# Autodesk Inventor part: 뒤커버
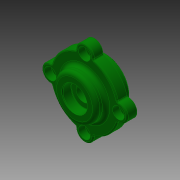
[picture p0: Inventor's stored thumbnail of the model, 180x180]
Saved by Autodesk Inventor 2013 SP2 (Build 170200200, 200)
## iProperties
Created: 2016-05
Part Number: 뒤커버
Document SubType Name: Modeling
Designer: mduedu
Density: 2.71 g/cm^3
Material: 알루미늄 6061
Author: mduedu
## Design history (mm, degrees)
sketch "스케치1"
  geometry: C1 r 20 at (0, 0); C2 r 27.5 at (0, 0); 1 further point
  constraints: 2 centre point, 2 coincident
  dimensions: "d33" = 55 diameter of C2; "d34" = 40 diameter of C1
extrude "돌출1" new body sketch "스케치1" distance "d0" = 8; taper "d1" = 0 deg
extrude "돌출2" join sketch "스케치1" distance "d2" = 8; taper "d3" = 0 deg; dims "d35" = 9, "d36" = 0
sketch "스케치6"
  geometry: C1 r 17.5 at (0, 0); 2 further points
  constraints: 2 coincident, 1 centre point
  dimensions: "d42" = 35 diameter of C1
extrude "돌출4" join sketch "스케치6" distance "d43" = 8; taper "d44" = 0 deg
sketch "스케치4"
  geometry: L1 (0, -9)-(0, 16); L2 (-15, -9)-(-15, 0); L3 (-15, 0)-(-10, 0); L4 (-10, 0)-(-10, 3); L5 (-10, 3)-(-6, 3); L6 (-6, 3)-(-6, 8.7); L7 (-6, 8.7)-(-10, 8.7); L8 (-10, 8.7)-(-10, 16); L9 (20, -9)-(-20, -9) reference; L10 (17.5, 16)-(-17.5, 16) reference; 1 further point
  constraints: 16 end point, 6 parallel, 3 point on line, 2 midpoint, 2 perpendicular, 1 vertical
  dimensions: "d15" = 30 diameter of L2 L1; "d16" = 20 diameter of L8 L1; "d18" = 9 distance of L2.start L2.end; "d19" = 3 distance of L3.end L4.end; "d20" = 20 diameter of L4 L1; "d21" = 12 diameter of L6 L1; "d45" = 7.3 distance of L7.end L8.end
revolve "회전1" sketch "스케치4" stored, may be unused: angle "d22" = 90 deg
fillet "모깎기2" dims "d23" = 3
fillet "모깎기3" dims "d24" = 0.3
chamfer "모따기2" distance "d46" = 1; stored, may be unused: second distance "d47" = 2, angle "d48" = 45 deg
sketch "스케치7"
  geometry: C1 r 7 at (0, 27.5); 2 further points
  constraints: 3 vertical alignment, 1 centre point, 2 other
  dimensions: "d54" = 14 diameter of C1
extrude "돌출5" join sketch "스케치7" stored distance "d55" = 10; taper "d56" = 0 deg
fillet "모깎기6" dims "d57" = 1
sketch "스케치10"
  geometry: C1 r 17.5 at (0, 0) reference; A1 r 27.5 centre (0, 0) between (26.395, 7.718) and (7.718, 26.395) reference; A2 r 1 centre (7.999, 27.355) between (6.999, 27.373) and (7.718, 26.395) reference; A3 r 7 centre (0, 27.5) between (6.999, 27.373) and (-6.999, 27.373) reference; A4 r 1 centre (-7.999, 27.355) between (-7.718, 26.395) and (-6.999, 27.373) reference; A5 r 27.5 centre (0, 0) between (-7.718, 26.395) and (-26.395, 7.718) reference; A6 r 1 centre (-27.355, 7.999) between (-27.373, 6.999) and (-26.395, 7.718) reference; A7 r 7 centre (-27.5, 0) between (-27.373, 6.999) and (-27.373, -6.999) reference; A8 r 1 centre (-27.355, -7.999) between (-26.395, -7.718) and (-27.373, -6.999) reference; A9 r 27.5 centre (0, 0) between (-26.395, -7.718) and (-7.718, -26.395) reference; A10 r 1 centre (-7.999, -27.355) between (-6.999, -27.373) and (-7.718, -26.395) reference; A11 r 7 centre (0, -27.5) between (-6.999, -27.373) and (6.999, -27.373) reference; A12 r 1 centre (7.999, -27.355) between (7.718, -26.395) and (6.999, -27.373) reference; A13 r 27.5 centre (0, 0) between (7.718, -26.395) and (26.395, -7.718) reference; A14 r 1 centre (27.355, -7.999) between (27.373, -6.999) and (26.395, -7.718) reference; A15 r 7 centre (27.5, 0) between (27.373, -6.999) and (27.373, 6.999) reference; A16 r 1 centre (27.355, 7.999) between (26.395, 7.718) and (27.373, 6.999) reference; 4 further points
  constraints: 3 coincident
hole "구멍3" sketch "스케치10" at (0, 27.5), (-27.5, 0), (0, -27.5), (27.5, 0) diameter "d81" = 5.5; stored, may be unused: countersink angle "d85" = 90 deg, drill point angle "d87" = 118 deg; dims "d82" = 6, "d83" = 9.5, "d84" = 5.4, "d86" = 8
fillet "모깎기7" dims "d61" = 1
fillet "모깎기8" dims "d88" = 3
chamfer "모따기3" distance "d76" = 0.7; stored, may be unused: second distance "d77" = 2, angle "d78" = 30 deg
node "솔리드1"
pattern_circular "원형 패턴1" dims angle "d59" = 360 deg
node "투영된 루프1"
